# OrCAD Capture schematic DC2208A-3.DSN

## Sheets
1 PAGE2: size A
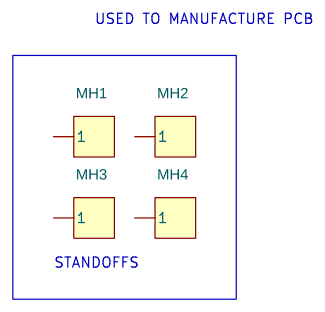
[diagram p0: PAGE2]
2 PAGE1: size Custom; title: BATTERY/SUPER-CAPACITOR; rev: 3; company: TM; note: BACKUP SWITCHOVER
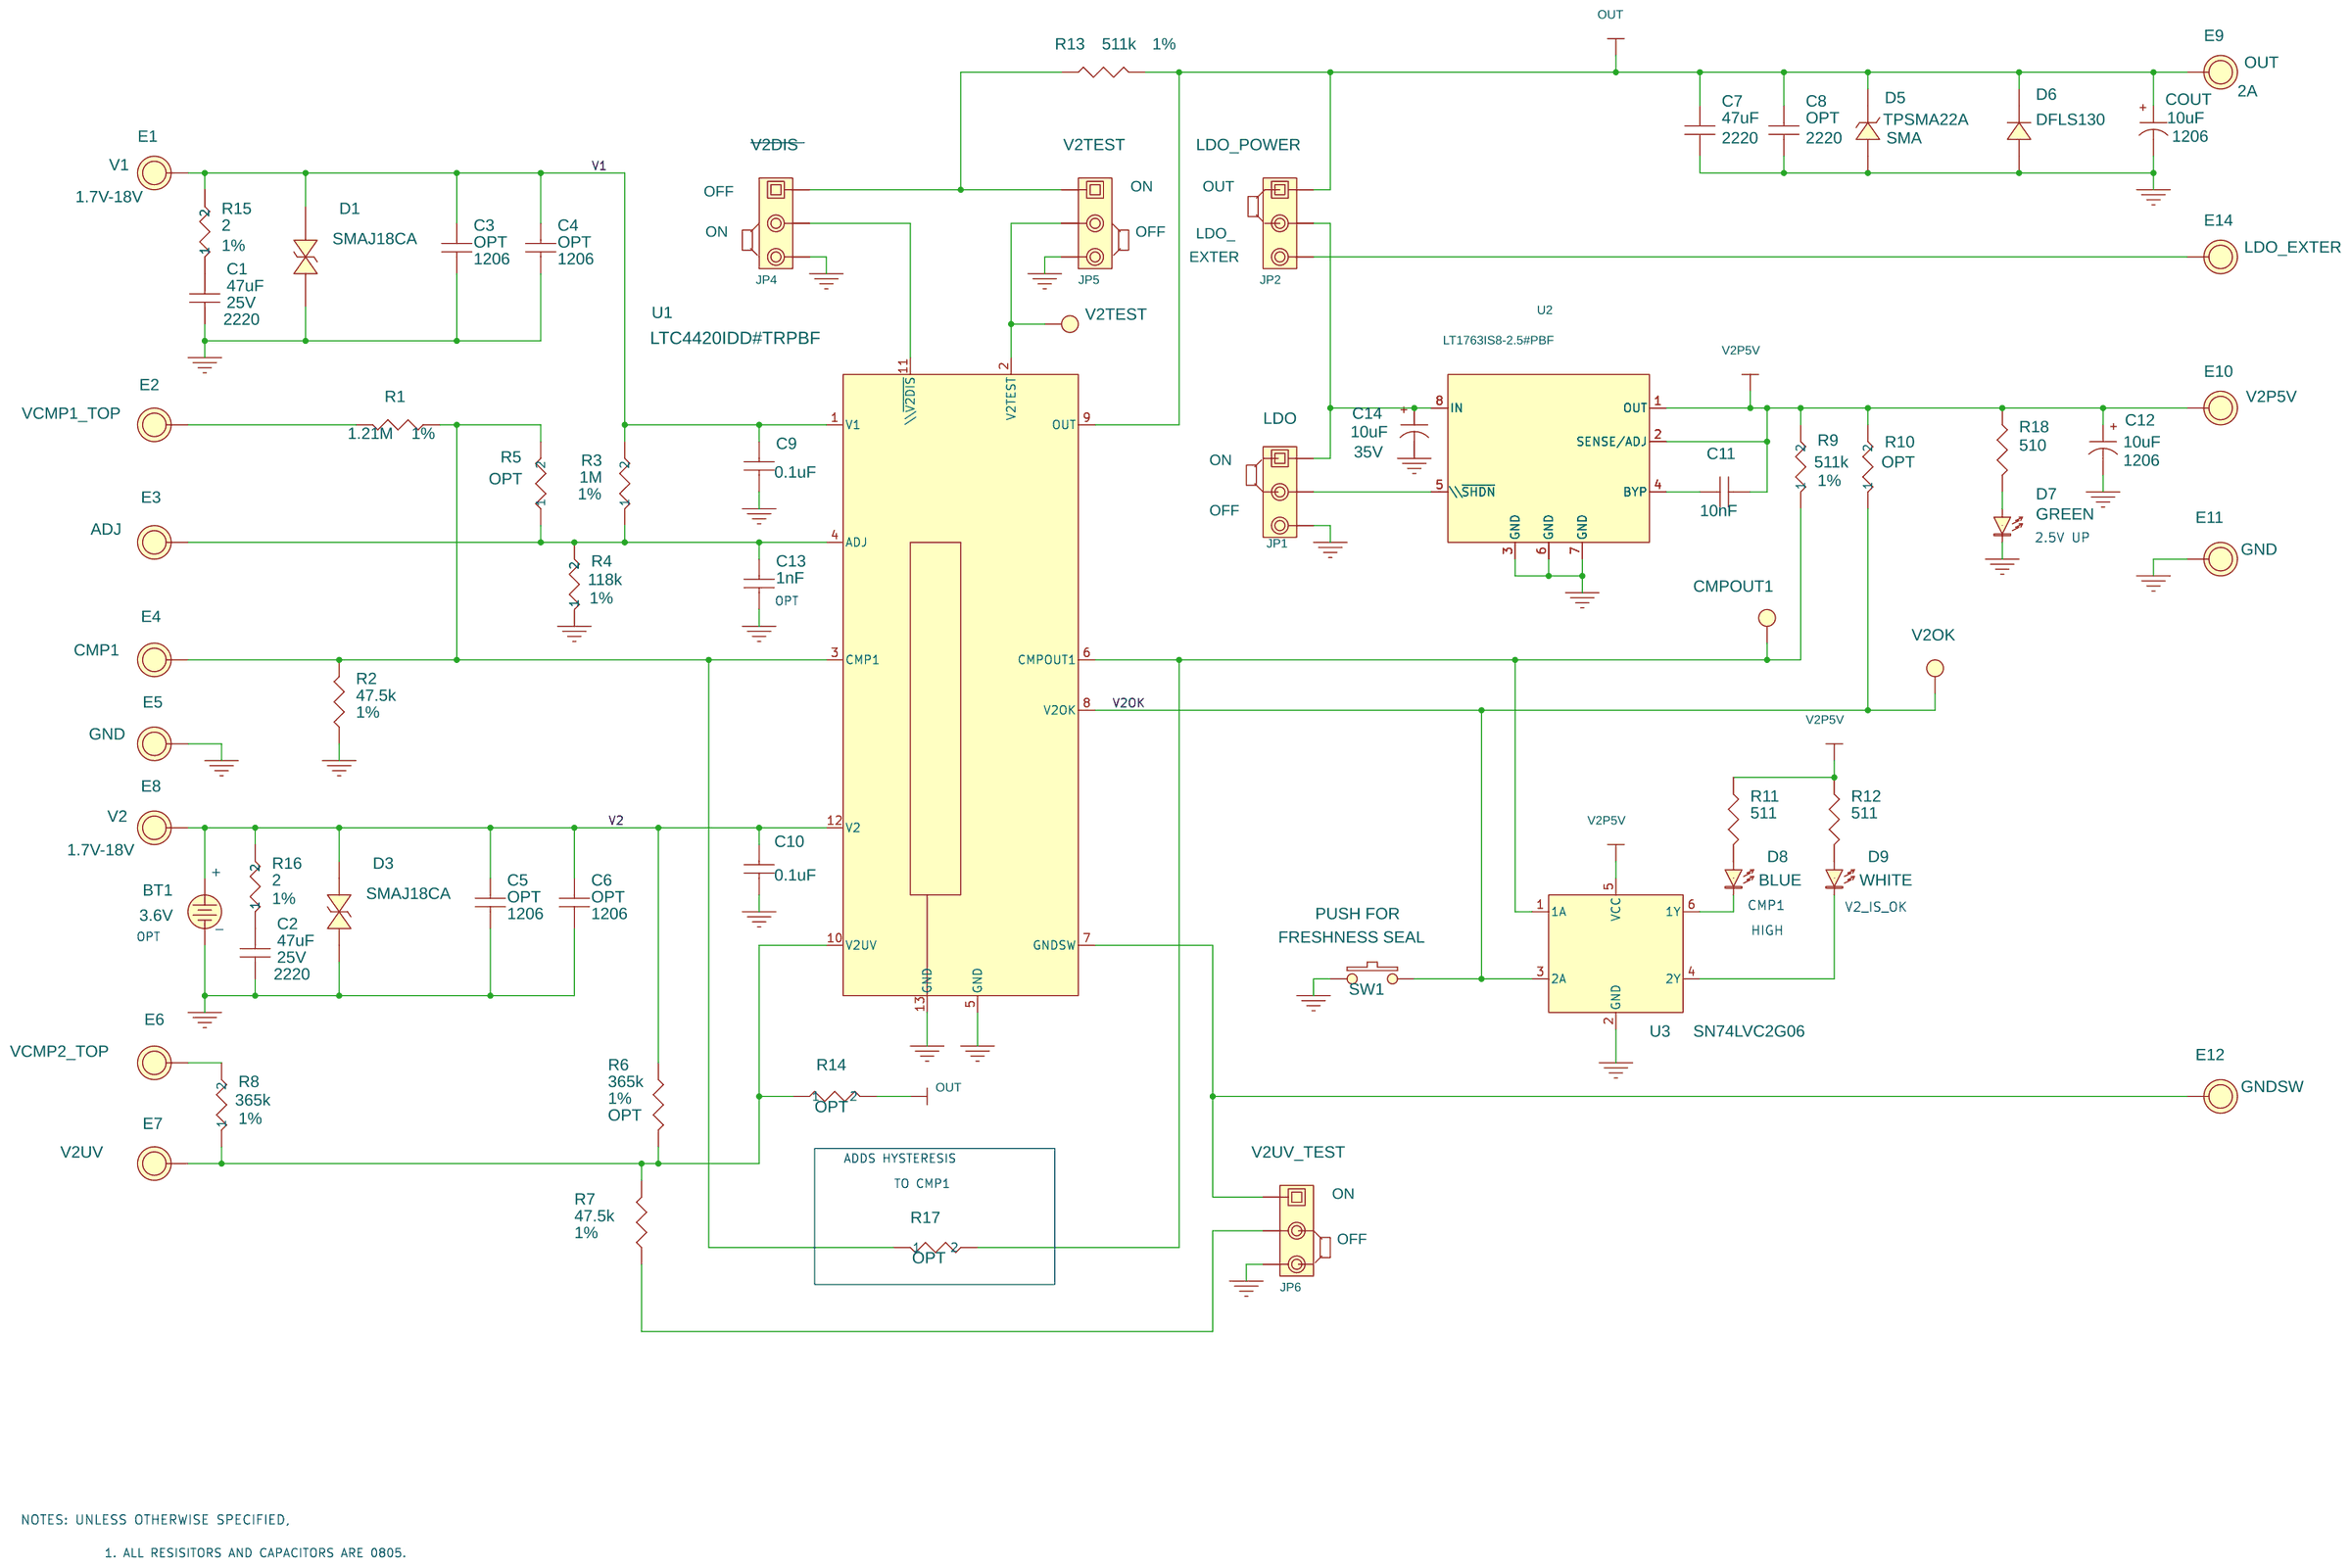
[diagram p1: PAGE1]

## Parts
sheet PAGE1
BT1  3.6V  [Bat_Hldr_20mm]
C1  47uF  [2220]
C2  47uF  [2220]
C3  OPT  [1206]
C4  OPT  [1206]
C5  OPT  [1206]
C6  OPT  [1206]
C7  47uF  [2220]
C8  OPT  [2220]
C9  0.1uF  [0805]
C10  0.1uF  [0805]
C11  10nF  [0805]
C12  10uF  [1206]
C13  1nF  [0805]
C14  10uF  [7343]
COUT  10uF  [1206]
D1  SMAJ18CA  [SMB]
D3  SMAJ18CA  [SMB]
D5  TPSMA22A  [SMA-DIODE]
D6  DFLS130  [POWERDI_123]
D7  GREEN  [LED_0603]
D8  BLUE  [LED_0603]
D9  WHITE  [LED_0603]
E1  1.7V-18V  [TP\MMX\2501-2]
E2  2.7V - 17V  [TP\MMX\2308-2]
E3  3.6V  [TP\MMX\2308-2]
E4  2.7V - 17V  [TP\MMX\2308-2]
E5  2.7V - 17V  [TP\MMX\2308-2]
E6  2A  [TP\MMX\2308-2]
E7  3A  [TP\MMX\2308-2]
E8  1.7V-18V  [TP\MMX\2501-2]
E9  2A  [TP\MMX\2501-2]
E10  2A  [TP\MMX\2308-2]
E11  2.7V - 17V  [TP\MMX\2501-2]
E12  2.7V - 17V  [TP\MMX\2308-2]
E14  2A  [TP\MMX\2501-2]
JP1  3 Pins 2mm Ctrs.  [SIP\3P\2MM]
JP2  3 Pins 2mm Ctrs.  [SIP\3P\2MM]
JP4  3 Pins 2mm Ctrs.  [SIP\3P\2MM]
JP5  3 Pins 2mm Ctrs.  [SIP\3P\2MM]
JP6  3 Pins 2mm Ctrs.  [SIP\3P\2MM]
R1  1.21M  [0805]
R2  47.5k  [0805]
R3  1M  [0805]
R4  118k  [0805]
R5  OPT  [0805]
R6  365k  [0805]
R7  47.5k  [0805]
R8  365k  [0805]
R9  511k  [0805]
R10  OPT  [0805]
R11  511  [0805]
R12  511  [0805]
R13  511k  [0805]
R14  OPT  [0805]
R15  2  [0805]
R16  2  [0805]
R17  OPT  [0805]
R18  510  [0805]
SW1  PUSH FOR  [SW-MJTP1250]
TP2  V2OK  [RP100]
TP3  CMPOUT1  [RP100]
TP4  V2TEST  [RP100]
U1  LTC4420IDD#TRPBF  [LT_DD12_3X3]
U2  LT1763IS8-2.5#PBF  [LT_S8]
U3  SN74LVC2G06  [FRCHLD_DCK]
XJP1  2mm Ctrs.
XJP2  2mm Ctrs.
XJP3  2mm Ctrs.
XJP4  2mm Ctrs.
XJP5  2mm Ctrs.
sheet PAGE2
MH1  CON1  [KEYSTONE_8831]
MH2  CON1  [KEYSTONE_8831]
MH3  CON1  [KEYSTONE_8831]
MH4  CON1  [KEYSTONE_8831]

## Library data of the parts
BT1 = BATTERY_1: HOLDER, BATTERY 20mm OPTION; Part Number: KEYSTONE 1066 OPTION
C1 C2 C7 = CAP_NP: CAP, 2220 47uF20% 25V X5R; FIELD1: 0805; Part Number: TDK CKG57NX5R1E476M500JH; Tolerance: X5R; Voltage: 25V
C3-C6 = CAP_NP: CAP, 1206 22uF 20% 6.3V X5R OPTION; FIELD1: 0805; Part Number: TAIYO YUDEN EMK316BJ226ML-T OPTION; Tolerance: X5R; Voltage: 6.3V
C8 = CAP_NP: CAP, 2220 OPTION; FIELD1: 0805; Part Number: OPTION; Tolerance: X5R; Voltage: 25V
C9 C10 = CAP_NP: CAP, 0805 0.1uF 10% 25V X5R; Part Number: AVX 08053D104KAT2A; VOLTAGE: 25V
C11 = CAP_NP: CAP, 0805 10nF 10% 16V X7R; Part Number: AVX 0805YC103KAT2A
C12 COUT = CAP+7343: CAP, 1206 10uF 20% 25V TANT; 1ST PART FIELD: 25V; 2ND PART FIELD: OPT; 4TH PART FIELD: [1]; Part Number: AVX F951E106MAAAQ2
C13 = CAP_NP: CAP, 0805 1nF 10% 50V X7R; Case: 1206; Part Number: AVX 08055C102KAT; Tolerance: NPO; Voltage: 50V
C14 = CAP+7343: CAP, 7343 10uF 10% 35V TANT; 1ST PART FIELD: 35V; 2ND PART FIELD: OPT; 4TH PART FIELD: [1]; 5TH PART FIELD: 1206; Part Number: AVX TPSD106K035R0300
D1 D3 = DIODE_BI-DIR_TRIG: DIODE, 600 WATT TRANSIENT VOLTAGE SUPPRESSOR; Part Number: LITTLEFUSE INC. SMAJ18CA
D5 = DIODE_ZENER: DIODE, 400W 22V TRANSIENT VOLTAGE SUPPRESSOR; FTPRNT: SMA; Part Number: VISHAY TPSMA22A
D6 = DIODE_0: DIODE, SCHOTTKY BARRIER RECTIFIER 30V 1.0A; Part Number: DIODES INC. DFLS130-7
D7 = DIODE-LED_2: LED, 0603 GREEN; Manufacturer: PANASONIC; Manufacturer P/N: LN1371SGTRP; Part Number: WURTH ELEKTRONIK 150060GS75000
D8 = DIODE-LED_2: LED, 0603 B LUE; Label: GREEN; Manufacturer: PANASONIC; Part Number: WURTH ELEKTRONIK 150060BS75000
D9 = DIODE-LED_2: LED, 0603 WHITE; Label: GREEN; Manufacturer: PANASONIC; Part Number: PANASONIC LNJ026X8ARA1
E1 = E_4: TURRET; INPUT: V1; Part Number: MILL-MAX 2501-2-00-80-00-00-07-0; STATUS: 1.6V, 1.8V, 2.0V OR 2.5V @ 15A
E2 = E_4: TURRET; INPUT: VCMP1_TOP; Part Number: MILL MAX 2308-2-00-80-00-00-07-0; STATUS: 1.6V, 1.8V, 2.0V OR 2.5V @ 15A
E3 = E_4: TURRET; INPUT: ADJ; Part Number: MILL MAX 2308-2-00-80-00-00-07-0; STATUS: 1.6V, 1.8V, 2.0V OR 2.5V @ 15A
E4 = E_4: TURRET; INPUT: CMP1; Part Number: MILL MAX 2308-2-00-80-00-00-07-0; STATUS: 1.6V, 1.8V, 2.0V OR 2.5V @ 15A
E5 = E_4: TURRET; INPUT: GND; Part Number: MILL MAX 2308-2-00-80-00-00-07-0; STATUS: 1.6V, 1.8V, 2.0V OR 2.5V @ 15A
E6 = E_4: TURRET; INPUT: VCMP2_TOP; Part Number: MILL MAX 2308-2-00-80-00-00-07-0; STATUS: 1.6V, 1.8V, 2.0V OR 2.5V @ 15A
E7 = E_4: TURRET; INPUT: V2UV; Part Number: MILL MAX 2308-2-00-80-00-00-07-0; STATUS: 1.6V, 1.8V, 2.0V OR 2.5V @ 15A
E8 = E_4: TURRET; INPUT: V2; Part Number: MILL-MAX 2501-2-00-80-00-00-07-0; STATUS: 1.6V, 1.8V, 2.0V OR 2.5V @ 15A
E9 = E_4: TURRET; INPUT: OUT; Part Number: MILL-MAX 2501-2-00-80-00-00-07-0; STATUS: 1.6V, 1.8V, 2.0V OR 2.5V @ 15A
E10 = E_4: TURRET; INPUT: V2P5V; Part Number: MILL MAX 2308-2-00-80-00-00-07-0; STATUS: 1.6V, 1.8V, 2.0V OR 2.5V @ 15A
E11 = E_4: TURRET; INPUT: GND; Part Number: MILL-MAX 2501-2-00-80-00-00-07-0; STATUS: 1.6V, 1.8V, 2.0V OR 2.5V @ 15A
E12 = E_4: TURRET; INPUT: GNDSW; Part Number: MILL MAX 2308-2-00-80-00-00-07-0; STATUS: 1.6V, 1.8V, 2.0V OR 2.5V @ 15A
E14 = E_4: TURRET; INPUT: LDO_EXTER; Part Number: MILL-MAX 2501-2-00-80-00-00-07-0; STATUS: 1.6V, 1.8V, 2.0V OR 2.5V @ 15A
JP1 = Samtec_TMM-103-02-L-S: HEADER, 2mm, 3PIN; 11th Part Field: OFF; 12th Part Field: LDO; 9th Part Field: ON; Part Number: SULLINS, NRPN031PAEN-RC
JP2 = Samtec_TMM-103-02-L-S: HEADER, 2mm, 3PIN; 11th Part Field: LDO_; 12th Part Field: LDO_POWER; 4th Part Field: EXTER; 9th Part Field: OUT; Part Number: SULLINS NRPN031PAEN-RC
JP4 = Samtec_TMM-103-02-L-S: HEADER, 2mm, 3PIN; 11th Part Field: ON; 12th Part Field: V2DIS; 9th Part Field: OFF; Part Number: SULLINS, NRPN031PAEN-RC
JP5 = Samtec_TMM-103-02-L-S: HEADER, 2mm, 3PIN; 11th Part Field: OFF; 12th Part Field: V2TEST; 9th Part Field: ON; Part Number: SULLINS, NRPN031PAEN-RC
JP6 = Samtec_TMM-103-02-L-S: HEADER, 2mm, 3PIN; 11th Part Field: OFF; 12th Part Field: V2UV_TEST; 9th Part Field: ON; Part Number: SULLINS, NRPN031PAEN-RC
R1 = RESISTOR: RES, 0805 1.21M PHMS 1% 1/18W; Part Number: VISHAY CRCW08051M21FKEA; Tol: 1%
R2 R7 = RESISTOR: RES, 0805 47.5k OHMS 1% 1/8W; Part Number: VISHAY CRCW080547K5FKEA; Tolerance: 1%
R3 = R_1: RES, 0805 1M OHMS 1% 1/8W; 5%: 1%; Part Number: VISHAY CRCW08051M00FKEA; Tol: 1%
R4 = R: RES, 0805 118K OHMS 1% 1/8W; 5%: 1%; Part Number: VISHAY CRCW0805118KFKEA; Tol: 1%
R5 = R_7: RES, 0805 69.8K OHMS 1% 1/8W OPTION; 5%: 1%; Part Number: VISHAY CRCW080569K8FKEA OPTION
R6 = RESISTOR: RES, 0805 365K OHMS 1% 1/8W OPTION; Part Number: VISHAY CRCW0805365KFKEA OPTION; Tol: 1%; Tolerance: OPT
R8 = R_2: RES, 0805 365K OHMS 1% 1/8W; 5%: 1%; Part Number: VISHAY CRCW0805365KFKEA; Tol: 1%
R9 = R_3: RES, 0805 511K OHMS 1% 1/8W; 5%: 1%; Part Number: VISHAY CRCW0805511KFKEA; Tol: 1%
R10 = R_4: RES, 0805 511K OHMS 1% 1/8W OPTION; 5%: 1%; Part Number: VISHAY CRCW0805511KFKEA OPTION; Tol: 1%
R11 R12 = RES0603_0: RES, 0805 511 OHMS 1% 1/8W; Manufacturer: ROHM; Manufacturer P/N: MCR03EZPFX4991; Part Number: VISHAY CRCW080511R0FKEA; Vendor: Digikey; Vendor P/N: RHM4.99KHCT-ND; Volts/Amps/Watts: 1/8
R13 = RES0603_0: RES, 0805 511K OHMS 1% 1/8W; Manufacturer: ROHM; Manufacturer P/N: MCR03EZPFX4991; Part Number: VISHAY CRCW0805511KFKEA; Tol: 1%; Vendor: Digikey; Vendor P/N: RHM4.99KHCT-ND; Volts/Amps/Watts: 1/8
R14 = R_8: RES, 0805 511K OHMS 1% 1/8W OPTION; 5%: 1%; Part Number: VISHAY CRCW0805511KFKEA OPTION; Tol: 1%
R15 = R_9: RES, 0805 2 OHMS 1% 1/8W; 5%: 1%; Part Number: VISHAY CRCW08052R00FNEA
R16 = R_6: RES, 0805 2 OHMS 1% 1/8W; 5%: 1%; Part Number: VISHAY CRCW08052R00FNEA
R17 = R_5: RES, 0805 1M OHMS 1% 1/8W OPTION; 5%: 1%; Part Number: VISHAY CRCW08051M00FKEA OPTION; Tol: 1%
R18 = RES0603_0: RES, 0805 510 OHMS 5% 1/8W; Manufacturer: ROHM; Manufacturer P/N: MCR03EZPFX4991; Part Number: VISHAY CRCW0805510RJNEA; Vendor: Digikey; Vendor P/N: RHM4.99KHCT-ND; Volts/Amps/Watts: 0.1w
SW1 = SW_PUSHBUTTON-SPST: SWITCH, MOMENTARY, PUSH BUTTON; Label: FRESHNESS SEAL; Part Number: WURTH 434 123 050 816
TP2-TP4 = T_POINT_R_0: PAD; Part Number: NONE
U1 = LTC4420IDD: IC, LTC4420IDD#TRPBF; Part Number: LINEAR TECH LTC4420IDD#TRPBF
U2 = LTC1763_0: IC, 500mA LOW NOISE LDO MICROPOWER REGULATOR; Part Number: LINEAR TECH LT1763IS8-2.5#PBF
U3 = SN74LVC2G06_0: IC, DUAL INVERTER BUFFER/DRIVER WITH OPEN-DRAIN OUTPUTS; Part Number: TEXAS INSTRUMENTS SN74LVC2G06DCKR
XJP1-XJP5 = Samtec_2SN-BK-G: SHUNT, 2mm; Part Number: SAMTEC 2SN-BK-G
MH1-MH4 = CON1: STANDOFF, SNAP ON

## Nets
GND: BT1.2(-) C1.2 C2.2 C3.2 C4.2 C5.2 C6.2 C7.2 C8.2 C9.2 C10.2 C12.2 C13.2 C14.2 COUT.2 D1.2 D3.2 D5.2(ANODE) D6.2(A) D7.1(K) E5.1(A) E11.1(A) JP1.3 JP4.3 JP5.3 JP6.3 R2.1 R4.1 SW1.2 U1.5(GND) U1.13(GND) U2.3(GND) U2.6(GND) U2.7(GND) U3.2(GND)
V1: C3.1 C4.1 C9.1 D1.1 E1.1(A) R3.2 R15.2 U1.1(V1)
V2: BT1.1(+) C5.1 C6.1 C10.1 D3.1 E8.1(A) R6.2 R16.2 U1.12(V2)
V2OK: R10.1 SW1.1 TP2.1(TP) U1.8(V2OK) U3.3(2A)
V2P5V: C11.2 C12.1 E10.1(A) R9.2 R10.2 R11.1 R12.1 R18.1 U2.1(OUT) U2.2(SENSE/ADJ) U3.5(VCC)
OUT: C7.1 C8.1 COUT.1 D5.1(CATHODE) D6.1(C) E9.1(A) JP2.1 R13.2 R14.2 U1.9(OUT)
N16873578: C13.1 E3.1(A) R3.1 R4.2 R5.1 U1.4(ADJ)
N16875418: E2.1(A) R1.1
N16875536: E4.1(A) R1.2 R2.2 R5.2 R17.1 U1.3(CMP1)
N16897180: C14.1 JP1.1 JP2.2 U2.8(IN)
N16900284: JP1.2 U2.5(\\~{SHDN})
N16905929: C11.1 U2.4(BYP)
N16911013: R9.1 R17.2 TP3.1(TP) U1.6(CMPOUT1) U3.1(1A)
N16915244: D7.2(A) R18.2
N16931666: D8.1(K) U3.6(1Y)
N16933198: D9.1(K) U3.4(2Y)
N17109323: E6.1(A) R8.2
N17109533: E7.1(A) R6.1 R7.2 R8.1 R14.1 U1.10(V2UV)
N17123373: E12.1(A) JP6.1 U1.7(GNDSW)
N17143701: JP4.1 JP5.1 R13.1
N17152273: JP4.2 U1.11(\\~{V2DIS})
N17152939: JP5.2 TP4.1(TP) U1.2(V2TEST)
N17249894: E14.1(A) JP2.3
N17267734: JP6.2 R7.1
N17336250: D9.2(A) R12.2
N17336252: C2.1 R16.1
N17336253: D8.2(A) R11.2
N17336254: C1.1 R15.1

Not connected (* = marked no-connect by the designer): MH1 1; MH2 1; MH3 1; MH4 1

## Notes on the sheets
sheet 1
- USED TO MANUFACTURE PCB
- STANDOFFS
sheet 2
- 2.5V UP
- OPT
- +
- CMP1
- V2_IS_OK
- -
- HIGH
- OPT
- ADDS HYSTERESIS
- TO CMP1
- NOTES: UNLESS OTHERWISE SPECIFIED,
- 1. ALL RESISITORS AND CAPACITORS ARE 0805.
